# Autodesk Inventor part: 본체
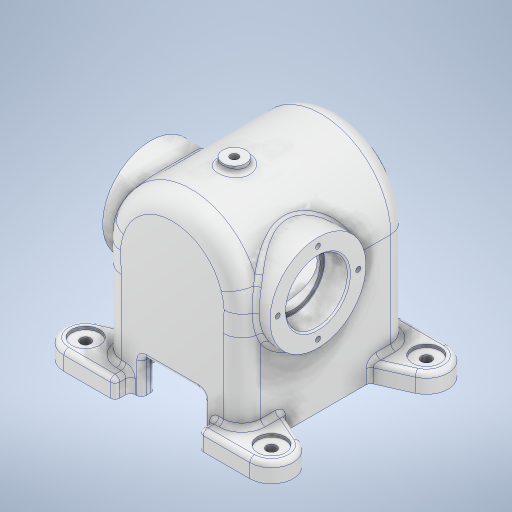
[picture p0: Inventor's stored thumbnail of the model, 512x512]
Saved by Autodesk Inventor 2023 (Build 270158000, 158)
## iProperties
Created: 2024-09
Part Number: 본체
Material: 알루미늄 6061
Document SubType Name: Modeling
Designer: asung
Density: 2.7 g/cm^3
Appearance: 알루미늄 - 평지
Mass: 1386.57 g
Surface Area: 1149.27 cm^2
Volume: 513.544 cm^3
Author: asung
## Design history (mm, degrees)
sketch "스케치1"
  geometry: C1 r 45 at (0, 0); 1 further point
  constraints: 1 centre point, 1 coincident
  dimensions: "d0" = 90 diameter of C1
extrude "돌출1" new body sketch "스케치1" distance "d1" = 108; taper "d2" = 0 deg
sketch "스케치2"
  geometry: C1 r 28.5 at (0, 0); 1 further point
  constraints: 1 centre point, 1 coincident
  dimensions: "d3" = 57 diameter of C1
extrude "돌출2" join sketch "스케치2" distance "d4" = 6; taper "d5" = 0 deg
sketch "스케치3"
  geometry: L1 (45, 108)-(45, 0) reference; L2 (45, 0)-(28.5, 0) reference; L3 (28.5, 0)-(28.5, -6) reference; L4 (28.5, -6)-(-28.5, -6) reference; L5 (-28.5, -6)-(-28.5, 0) reference; L6 (-28.5, 0)-(-45, 0) reference; L7 (-45, 0)-(-45, 108) reference; L8 (-45, 108)-(45, 108) reference; C1 r 7.5 at (0, 68); 1 further point
  constraints: 1 centre point, 1 vertical alignment
  dimensions: "d6" = 15 diameter of C1; "d7" = 74 distance from line of C1.centre L4
extrude "돌출3" join sketch "스케치3" stored distance "d8" = 98; taper "d9" = 0 deg
sketch "스케치4"
  geometry: L1 (-28.5, -6)-(-28.5, 0) reference; L2 (-28.5, 0)-(-45, 0) reference; L3 (-45, 0)-(-45, 60.5) reference; L4 (-45, 60.5)-(-49, 60.5) reference; L5 (-49, 60.5)-(-49, 75.5) reference; L6 (-49, 75.5)-(-45, 75.5) reference; L7 (-45, 75.5)-(-45, 108) reference; L8 (-45, 108)-(45, 108) reference; L9 (45, 108)-(45, 75.5) reference; L10 (45, 75.5)-(49, 75.5) reference; L11 (49, 75.5)-(49, 60.5) reference; L12 (49, 60.5)-(45, 60.5) reference; L13 (45, 60.5)-(45, 0) reference; L14 (45, 0)-(28.5, 0) reference; L15 (28.5, 0)-(28.5, -6) reference; L16 (28.5, -6)-(-28.5, -6) reference; C1 r 31 at (0, 68); 2 further points
  constraints: 1 centre point, 1 horizontal alignment, 1 midpoint, 1 vertical alignment
  dimensions: "d10" = 62 diameter of C1
  node "절단 모서리 투영2"
sketch "스케치5"
  geometry: 1 further point
sketch "스케치6"
  geometry: L1 (-28.5, -6)-(-28.5, 0) reference; L2 (-28.5, 0)-(-45, 0) reference; L3 (-45, 0)-(-45, 60.5) reference; L4 (-45, 60.5)-(-49, 60.5) reference; L5 (-49, 60.5)-(-49, 75.5) reference; L6 (-49, 75.5)-(-45, 75.5) reference; L7 (-45, 75.5)-(-45, 108) reference; L8 (-45, 108)-(45, 108) reference; L9 (45, 108)-(45, 75.5) reference; L10 (45, 75.5)-(49, 75.5) reference; L11 (49, 75.5)-(49, 60.5) reference; L12 (49, 60.5)-(45, 60.5) reference; L13 (45, 60.5)-(45, 0) reference; L14 (45, 0)-(28.5, 0) reference; L15 (28.5, 0)-(28.5, -6) reference; L16 (28.5, -6)-(-28.5, -6) reference; L17 (36, 66.5)-(36, 96); L18 (33, 99)-(-36, 99); L19 (-36, 99)-(-36, 69.5); L20 (-36, 69.5)-(-36, 9); L21 (-36, 9)-(-19.5, 9); L22 (19.5, 9)-(33, 9); L23 (36, 12)-(36, 96); L24 (19.5, 9)-(-19.5, 9); L25 (45, 108)-(-45, 108) reference; L26 (0, 108)-(0, 0); A1 r 3 centre (33, 96) between (36, 96) and (33, 99); A2 r 3 centre (33, 96) between (36, 96) and (33, 99); A3 r 3 centre (33, 12) between (33, 9) and (36, 12); 2 further points
  constraints: 18 end point, 6 point on circle, 6 tangent, 3 centre point, 2 point on line, 1 concentric, 1 horizontal, 1 midpoint, 1 vertical, 5 other
  dimensions: "d13" = 9 distance between parallel lines of L9 L17; "d14" = 3 radius of A1; "d15" = 3 radius of A3 (derived)
revolve "회전1" sketch "스케치6" stored, may be unused: angle "d16" = 90 deg
sketch "스케치7"
  geometry: 1 further point
hole "구멍1" sketch "스케치7" at (0, 0) diameter "d17" = 33; stored, may be unused: countersink angle "d21" = 90 deg, drill point angle "d23" = 118 deg; dims "d18" = 11, "d19" = 4, "d20" = 2, "d22" = 16
node "작업 평면2"
node "작업 평면3"
sketch "스케치10"
  geometry: C1 r 7.5 at (0, 0) reference; 1 further point
hole "구멍4" sketch "스케치10" at (0, 0) diameter "d38" = 5.1881; stored, may be unused: countersink angle "d42" = 90 deg, drill point angle "d44" = 118 deg; dims "d39" = 15, "d40" = 40, "d41" = 16, "d43" = 16
sketch "스케치11"
  geometry: C1 r 7.5 at (0, 0) reference; 1 further point
hole "구멍5" sketch "스케치11" at (0, 0) diameter "d45" = 5.1881; stored, may be unused: countersink angle "d49" = 90 deg, drill point angle "d51" = 118 deg; dims "d46" = 15, "d47" = 4, "d48" = 2, "d50" = 16
node "작업 평면4"
sketch "스케치13"
  geometry: L1 (0, 0)-(0, 23)
  constraints: 2 end point, 1 vertical
  dimensions: "d63" = 23 distance of L1.start L1.end
hole "구멍7" sketch "스케치13" at (0, 23) diameter "d64" = 3.242; stored, may be unused: countersink angle "d68" = 90 deg, drill point angle "d70" = 118 deg; dims "d65" = 8, "d66" = 4, "d67" = 2, "d69" = 10
node "작업 평면1"
sketch "스케치14"
  geometry: L1 (-60, -50)-(60, -50); L2 (60, -50)-(60, 78); L3 (60, 78)-(-60, 78); L4 (-60, 78)-(-60, -50); L5 (-60, -50)-(60, 78); L6 (60, -50)-(-60, 78); L7 (-45, -40)-(45, -40) reference; L8 (-60, -36)-(60, -36); L9 (60, 64)-(-60, 64); L10 (60, -50)-(27, -50); L11 (27, -50)-(27, -36); L12 (65.693, -23.21)-(45, -14); L13 (45, 68)-(45, -40) reference; L14 (60, 14)-(85.179, 14); L15 (60, 78)-(27, 78); L16 (27, 78)-(27, 64); L17 (65.693, 51.21)-(45, 42); L18 (0, -50)-(0, -59.804); L19 (-45, 68)-(-45, -40) reference; L20 (-45, 68)-(45, 68) reference; L21 (-60, -50)-(-27, -50); L22 (-60, 78)-(-27, 78); L23 (-27, -50)-(-27, -36); L24 (-65.693, -23.21)-(-45, -14); L25 (-65.693, 51.21)-(-45, 42); L26 (-27, 78)-(-27, 64); L27 (36, -40)-(36, 59); L28 (36, 59)-(-36, 59); L29 (-36, 59)-(-36, -40); L30 (-45, -31)-(45, -31); A1 r 14 centre (60, -36) between (60, -50) and (65.693, -23.21); A2 r 14 centre (60, 64) between (65.693, 51.21) and (60, 78); A3 r 14 centre (-60, 64) between (-65.693, 51.21) and (-60, 78); 14 further points
  constraints: 52 end point, 14 symmetric about line, 6 point on circle, 5 parallel, 4 midpoint, 4 point on line, 3 centre point, 2 coincident, 2 horizontal, 2 perpendicular, 1 tangent, 1 vertical, 1 vertical alignment, 7 other
  dimensions: "d75" = 120 distance of L3.end L2.end; "d76" = 128 distance of L2.end L1.end; "d77" = 10 distance between parallel lines of L7 L1; "d78" = 14 distance between parallel lines of L1 L8; "d79" = 14 distance between parallel lines of L3 L9; "d80" = 28 diameter of A1; "d81" = 18 distance between parallel lines of L13 L11; "d82" = 36 vertical distance of L12.end L1.end; "d83" = 40.17924 distance from line of L14.end L13; "d84" = 15 distance from line of L9.start L13; "d85" = 24.7897 distance from line of point (20.21, -50) L13; "d86" = 127.80376 distance from line of L18.end L20; "d87" = 105 distance from line of L9.end L13; "d88" = 105 distance from line of L8.start L13; "d89" = 9 distance between parallel lines of L13 L27; "d90" = 9 distance between parallel lines of L7 L30
extrude "돌출5" join sketch "스케치14" distance "d91" = 12; taper "d92" = 0 deg
sketch "스케치15"
  geometry: L1 (36, -31)-(36, 59) reference; L2 (36, 59)-(-36, 59) reference; L3 (-36, 59)-(-36, -31) reference; L4 (-36, -31)-(36, -31) reference; L5 (45, -14)-(65.693, -23.21) reference; L6 (60, -50)-(27, -50) reference; L7 (27, -50)-(27, -40) reference; L8 (27, -40)-(-27, -40) reference; L9 (-27, -40)-(-27, -50) reference; L10 (-27, -50)-(-60, -50) reference; L11 (-65.693, -23.21)-(-45, -14) reference; L12 (-45, -14)-(-45, 42) reference; L13 (-45, 42)-(-65.693, 51.21) reference; L14 (-60, 78)-(-27, 78) reference; L15 (-27, 78)-(-27, 68) reference; L16 (-27, 68)-(27, 68) reference; L17 (27, 68)-(27, 78) reference; L18 (27, 78)-(60, 78) reference; L19 (65.693, 51.21)-(45, 42) reference; L20 (45, 42)-(45, -14) reference; L21 (-45, -40)-(-45, 68); L22 (-45, 68)-(45, 68); L23 (45, 68)-(45, -40); L24 (45, -40)-(-45, -40); A1 r 14 centre (60, -36) between (60, -50) and (65.693, -23.21) reference; A2 r 14 centre (-60, -36) between (-65.693, -23.21) and (-60, -50) reference; A3 r 14 centre (-60, 64) between (-60, 78) and (-65.693, 51.21) reference; A4 r 14 centre (60, 64) between (65.693, 51.21) and (60, 78) reference; 9 further points
  constraints: 8 end point, 3 other
  dimensions: "d93" = 90 distance of L23.end L21.start
extrude "돌출6" join sketch "스케치15" stored distance "d94" = 12; taper "d95" = 0 deg
sketch "스케치16"
  geometry: L1 (-20, -53)-(20, -53); L2 (20, -53)-(20, -76); L3 (20, -76)-(-20, -76); L4 (-20, -76)-(-20, -53); L5 (-20, -53)-(20, -76); L6 (20, -53)-(-20, -76); L7 (-27, -76)-(27, -76) reference; 3 further points
  constraints: 12 end point, 4 midpoint, 2 parallel, 1 horizontal, 1 perpendicular
  dimensions: "d96" = 40 distance of L2.end L3.end; "d97" = 23 distance of L1.end L2.end
extrude "돌출7" cut sketch "스케치16" extent not by distance; stored distance "d98" = 0; taper "d99" = 0 deg
sketch "스케치17"
  geometry: L1 (74, -76)-(60, -76) reference; 3 further points
  constraints: 1 vertical alignment, 1 other
  dimensions: "d100" = 35 distance from line of L1 point (0, -41)
feature "엠보싱1" sketch "스케치17" dims "d0" = 90, "d101" = 0.5, "d102" = 0
sketch "스케치18"
  geometry: L1 (-27, -40)-(-45, -40) reference; L2 (-45, -40)-(-45, -14) reference; L3 (-45, -14)-(-65.693, -23.21) reference; L4 (-60, -50)-(-27, -50) reference; L5 (-27, -50)-(-27, -40) reference; L6 (-45, 68)-(-27, 68) reference; L7 (-27, 68)-(-27, 78) reference; L8 (-27, 78)-(-60, 78) reference; L9 (-65.693, 51.21)-(-45, 42) reference; L10 (-45, 42)-(-45, 68) reference; L11 (45, 68)-(45, 42) reference; L12 (45, 42)-(65.693, 51.21) reference; L13 (60, 78)-(27, 78) reference; L14 (27, 78)-(27, 68) reference; L15 (27, 68)-(45, 68) reference; L16 (45, -14)-(45, -40) reference; L17 (45, -40)-(27, -40) reference; L18 (27, -40)-(27, -50) reference; L19 (27, -50)-(60, -50) reference; L20 (65.693, -23.21)-(45, -14) reference; A1 r 14 centre (-60, -36) between (-65.693, -23.21) and (-60, -50) reference; A2 r 14 centre (-60, 64) between (-60, 78) and (-65.693, 51.21) reference; A3 r 14 centre (60, 64) between (65.693, 51.21) and (60, 78) reference; A4 r 14 centre (60, -36) between (60, -50) and (65.693, -23.21) reference; 1 further point
hole "구멍8" sketch "스케치18" at (-60, -36), (60, -36), (60, 64), (-60, 64) diameter "d103" = 6.6; stored, may be unused: countersink angle "d107" = 90 deg, drill point angle "d109" = 118 deg; dims "d104" = 6, "d105" = 18, "d106" = 2, "d108" = 8
node "작업 평면5"
sketch "스케치19"
  geometry: L1 (0, 0)-(0, 108) reference; L2 (-28.5, -6)-(28.5, -6) reference; C1 r 31 at (0, 68)
  constraints: 1 centre point, 1 point on line
  dimensions: "d111" = 62 diameter of C1; "d112" = 74 distance from line of L2 C1.centre
extrude "돌출8" join sketch "스케치19" stored distance "d113" = 10; taper "d114" = 0 deg
sketch "스케치20"
  geometry: C1 r 31 at (0, 0) reference; 2 further points
  constraints: 1 coincident
hole "구멍9" sketch "스케치20" at (0, 0) diameter "d115" = 35; stored, may be unused: countersink angle "d119" = 90 deg, drill point angle "d121" = 118 deg; dims "d116" = 6, "d117" = 40, "d118" = 16, "d120" = 8
sketch "스케치21"
  geometry: C1 r 31 at (0, 0) reference; 2 further points
  constraints: 1 coincident
hole "구멍10" sketch "스케치21" at (0, 0) diameter "d122" = 35; stored, may be unused: countersink angle "d126" = 90 deg, drill point angle "d128" = 118 deg; dims "d123" = 6, "d124" = 40, "d125" = 16, "d127" = 8
sketch "스케치22"
  geometry: L1 (0, 0)-(0, 26); C1 r 31 at (0, 0) reference; 1 further point
  constraints: 2 end point, 1 vertical
  dimensions: "d129" = 26 distance of L1.start L1.end
hole "구멍11" sketch "스케치22" at (0, 26) diameter "d130" = 3.242; stored, may be unused: countersink angle "d134" = 90 deg, drill point angle "d136" = 118 deg; dims "d131" = 8, "d132" = 40, "d133" = 16, "d135" = 10
chamfer "모따기1" distance "d140" = 1; stored, may be unused: second distance "d141" = 2, angle "d142" = 45 deg
fillet "모깎기1" dims "d143" = 0.3
fillet "모깎기2" dims "d144" = 12
fillet "모깎기3" dims "d145" = 3
fillet "모깎기4" dims "d146" = 3
fillet "모깎기5" dims "d147" = 3
node "솔리드1"
pattern_circular "원형 패턴2" dims angle "d72" = 360 deg
mirror "미러2"
pattern_circular "원형 패턴3" dims angle "d138" = 360 deg
mirror "미러3"
node "투영된 루프3"
node "투영된 루프4"
node "투영된 루프6"
node "투영된 루프7"
node "투영된 루프8"
node "투영된 루프9"
node "절단 모서리 투영1"
node "절단 모서리 투영3"
node "절단 모서리 투영4"
feature "A9D066F2-1C7D-4E18-AEED-F7BC21143FA4" dims "d17" = 33, "d18" = 11, "d19" = 4, "d20" = 2, "d21" = 90 deg, "d22" = 16, "d23" = 118 deg
other parameters: "d74" = -125, "d110" = 54
